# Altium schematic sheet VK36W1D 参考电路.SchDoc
size A4
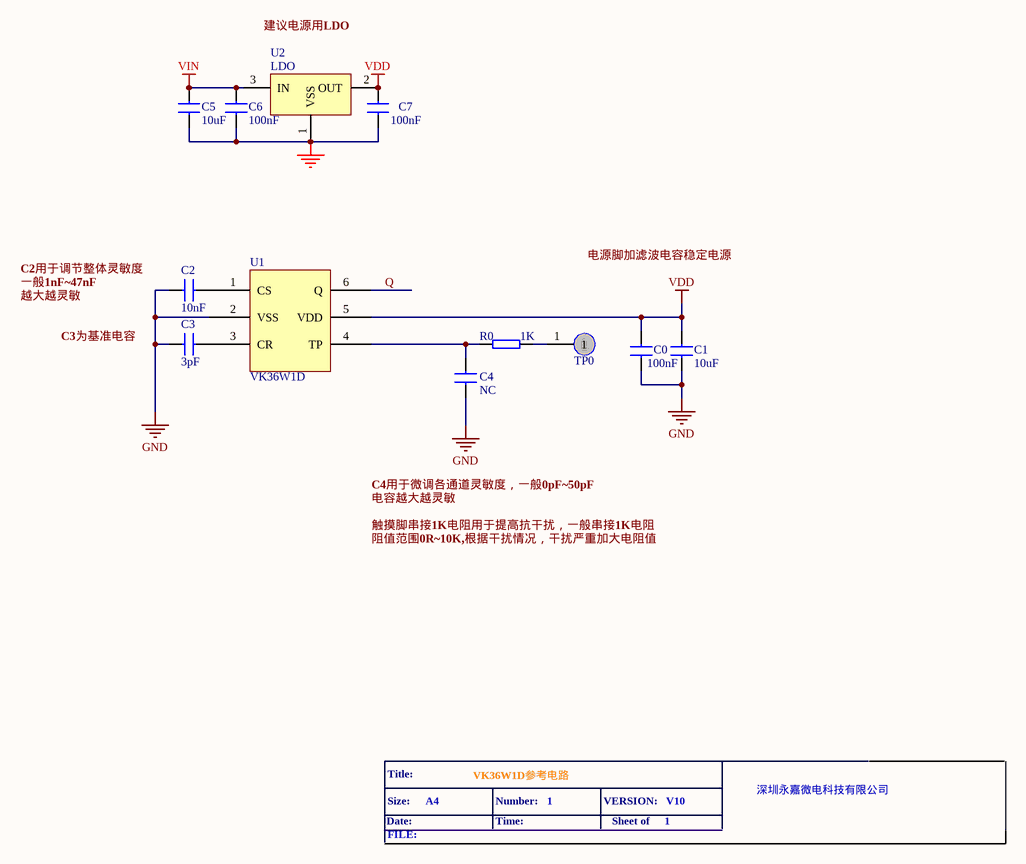
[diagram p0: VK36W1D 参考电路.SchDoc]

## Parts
C0  100nF  [0603-C]
C1  10uF  [0603-C]
C2  value 10nF  [0603-C]  (hidden comment: 10uF)
C3  value 3pF  [0603-C]  (hidden comment: 10uF)
C4  value NC  [0603-C]  (hidden comment: 10uF)
C5  10uF  [0805-C]
C6  100nF  [0805-C]
C7  100nF  [0805-C]
R0  1K  [0603-R]
TP0  TPAD  [TP-PAD0]  (value not drawn)
U1  VK36W1D
U2  LDO  [SOT-23]

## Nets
GND: C0.2 C1.2 C2.2 C3.2 C4.1 C5.2 C6.2 C7.2 U1.2(VSS) U2.1(VSS)
VDD: C0.1 C1.1 C7.1 U1.5(VDD) U2.2(OUT)
VIN: C5.1 C6.1 U2.3(IN)
Q: U1.6(Q)
NetC2_1: C2.1 U1.1(CS)
NetC3_1: C3.1 U1.3(CR)
NetC4_2: C4.2 R0.2 U1.4(TP)
NetR0_1: R0.1 TP0.1

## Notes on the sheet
- 建议电源用LDO
- C2用于调节整体灵敏度
- 一般1nF~47nF
- 电源脚加滤波电容稳定电源
- 越大越灵敏
- C3为基准电容
- C4用于微调各通道灵敏度，一般0pF~50pF
- 触摸脚串接1K电阻用于提高抗干扰，一般串接1K电阻
- 阻值范围0R
  0K,根据干扰情况，干扰严重加大电阻值
- 电容越大越灵敏
- Date:
- Title:
- Size:
- A4
- VK36W1D参考电路
- Number:
- Time:
- 1
- VERSION:
- Sheet of
- V10
- 深圳永嘉微电科技有限公司
- FILE:

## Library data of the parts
C0-C7 = CAP: Capacitor
R0 = RES: Resistor
TP0 = TPAD: TESTING
U2 = V6206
